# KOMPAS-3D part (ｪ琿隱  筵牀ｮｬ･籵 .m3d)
File: created 08.10.2017 17:00:22, last saved 09.10.2017 23:28:29.
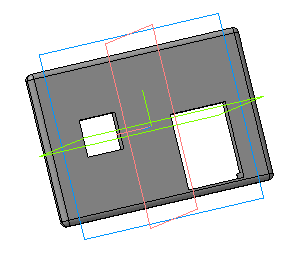
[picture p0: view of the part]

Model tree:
1. Эскиз:2
2. Операция выдавливания:2
     Толщина стенки 1 = 1.5; Расстояние 1 = 3
3. Эскиз:3
4. Операция выдавливания:3
     Толщина стенки 1 = 1.5; Толщина стенки 2 = 1.5; Расстояние 1 = 3.5
5. Эскиз:4
6. Вырезать элемент выдавливания:1
     Расстояние 2 = 2; Расстояние 1 = 18.5
7. Скругление:4
     Радиус = 1
8. Эскиз:8
9. Вырезать элемент выдавливания:2
     Расстояние 2 = 2; Расстояние 1 = 18.5
10. Эскиз:9
11. Вырезать элемент выдавливания:3
     Расстояние 2 = 2; Расстояние 1 = 18.5
12. Операция выдавливания:4
     Расстояние 1 = 0.2
13. Операция выдавливания:5
     Расстояние 1 = 0.2
14. Операция выдавливания:6
     Расстояние 1 = 0.2
15. Операция выдавливания:7
     Расстояние 1 = 0.2
16. Скругление:5
     Радиус = 1.5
